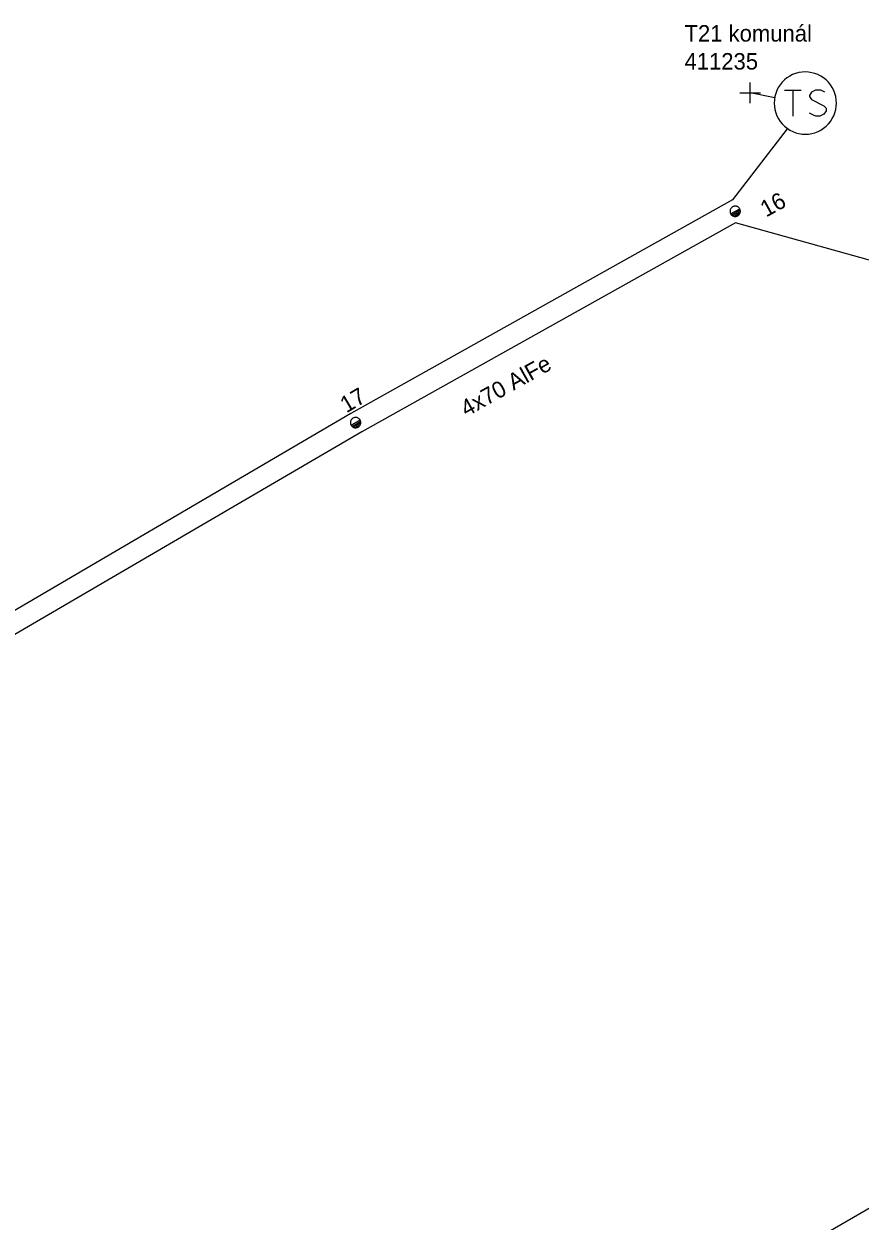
# Model space of a CAD drawing. Extents: x -540466 to -537383, y -1184038 to -1179972.
# Drawn here: x -537804.1 to -537753.3, y -1180377.4 to -1180304.7 of the extents above; entities that cross this region are included whole.
import ezdxf

# ---------------------------------------------------------------- set-up
doc = ezdxf.new("R2010")
doc.units = 0
for name, color, linetype in [('Vrstva 1', 7, 'Continuous'), ('Vrstva 13', 7, 'Continuous'), ('Vrstva 14', 7, 'Continuous'), ('Vrstva 2', 7, 'Continuous'), ('Vrstva 25', 7, 'Continuous'), ('Vrstva 26', 7, 'Continuous'), ('Vrstva 27', 7, 'Continuous'), ('Vrstva 34', 7, 'Continuous'), ('Vrstva 50', 7, 'Continuous'), ('Vrstva 59', 7, 'Continuous'), ('Vrstva 6', 7, 'Continuous'), ('Vrstva 8', 7, 'Continuous')]:
    doc.layers.add(name, color=color, linetype=linetype)

# ---------------------------------------------------------------- blocks, each defined once
blk = doc.blocks.new('NN440')
at = {"layer": 'Vrstva 2'}
for points in [[(0.63, 0), (0.63, 0.06), (0.62, 0.13), (0.6, 0.19), (0.58, 0.25), (0.55, 0.31), (0.51, 0.37), (0.47, 0.42), (0.42, 0.46), (0.37, 0.51), (0.32, 0.54), (0.26, 0.57), (0.2, 0.59), (0.13, 0.61), (0.07, 0.62), (0, 0.63), (-0.06, 0.62), (-0.13, 0.61), (-0.19, 0.59), (-0.26, 0.57), (-0.31, 0.54), (-0.37, 0.51), (-0.42, 0.46), (-0.47, 0.42), (-0.51, 0.37), (-0.54, 0.31), (-0.57, 0.25), (-0.6, 0.19), (-0.62, 0.13), (-0.63, 0.06), (-0.63, 0), (-0.63, -0.07), (-0.62, -0.14), (-0.6, -0.2), (-0.57, -0.26), (-0.54, -0.32), (-0.51, -0.37), (-0.47, -0.43), (-0.42, -0.47), (-0.37, -0.51), (-0.31, -0.55), (-0.26, -0.58), (-0.19, -0.6), (-0.13, -0.62), (-0.06, -0.63), (0, -0.63), (0.07, -0.63), (0.13, -0.62), (0.2, -0.6), (0.26, -0.58), (0.32, -0.55), (0.37, -0.51), (0.42, -0.47), (0.47, -0.43), (0.51, -0.37), (0.55, -0.32), (0.58, -0.26), (0.6, -0.2), (0.62, -0.14), (0.63, -0.07), (0.63, 0)], [(-0.63, 0), (0.63, 0)], [(-0.6, -0.18), (0.57, -0.18)], [(-0.51, -0.32), (0.5, -0.32)], [(-0.37, -0.47), (0.35, -0.47)]]:
    blk.add_lwpolyline(points, dxfattribs=at)
blk = doc.blocks.new('NN800')
at = {"layer": 'Vrstva 1'}
for points in [[(-0.442, 0.442), (0.442, -0.442)], [(-0.442, -0.442), (0.442, 0.442)]]:
    blk.add_lwpolyline(points, dxfattribs=at)
blk = doc.blocks.new('NN610')
at = {"layer": 'Vrstva 6'}
for points in [[(1.883, -0.001), (1.872, 0.196), (1.841, 0.392), (1.79, 0.583), (1.718, 0.768), (1.629, 0.943), (1.521, 1.109), (1.397, 1.263), (1.257, 1.403), (1.103, 1.527), (0.937, 1.635), (0.761, 1.725), (0.577, 1.796), (0.19, 1.878), (0.19, 1.878), (-0.007, 1.889), (-0.205, 1.878), (-0.401, 1.847), (-0.591, 1.796), (-0.777, 1.725), (-0.952, 1.635), (-1.118, 1.527), (-1.272, 1.403), (-1.412, 1.263), (-1.536, 1.109), (-1.644, 0.943), (-1.734, 0.768), (-1.805, 0.583), (-1.856, 0.392), (-1.887, 0.196), (-1.898, -0.001), (-1.887, -0.199), (-1.856, -0.395), (-1.805, -0.585), (-1.734, -0.77), (-1.644, -0.946), (-1.536, -1.112), (-1.411, -1.266), (-1.272, -1.405), (-1.118, -1.53), (-0.952, -1.638), (-0.776, -1.728), (-0.591, -1.799), (-0.401, -1.85), (-0.205, -1.881), (-0.007, -1.892), (0.19, -1.881), (0.385, -1.85), (0.577, -1.799), (0.761, -1.728), (0.937, -1.638), (1.103, -1.53), (1.257, -1.405), (1.397, -1.266), (1.521, -1.112), (1.629, -0.946), (1.718, -0.77), (1.79, -0.585), (1.841, -0.395), (1.872, -0.199), (1.883, -0.001)], [(-1.269, 0.782), (-0.261, 0.782)], [(-0.765, 0.782), (-0.765, -0.792)], [(1.188, 0.656), (0.936, 0.782), (0.621, 0.782), (0.369, 0.656), (0.243, 0.468), (0.243, 0.404), (0.369, 0.216), (1.125, -0.162), (1.251, -0.32), (1.251, -0.478), (1.125, -0.666), (0.873, -0.792), (0.621, -0.792), (0.495, -0.73), (0.243, -0.604)]]:
    blk.add_lwpolyline(points, dxfattribs=at)

msp = doc.modelspace()

# ---------------------------------------------------------------- linework, layer by layer
at = {"layer": 'Vrstva 1'}
msp.add_lwpolyline([(-537718.591, -1180328.331), (-537733.903, -1180324.349), (-537760.902, -1180316.828), (-537783.57, -1180329.507), (-537807.649, -1180343.561)], dxfattribs=at)
at = {"layer": 'Vrstva 50'}
msp.add_lwpolyline([(-537749.755, -1180374.876), (-537764.526, -1180383.433), (-537774.672, -1180385.885), (-537782.62, -1180390.235)], dxfattribs=at)
at = {"layer": 'Vrstva 59'}
msp.add_lwpolyline([(-537758.502, -1180309.229), (-537760.009, -1180308.927)], dxfattribs=at)
at = {"layer": 'Vrstva 8'}
msp.add_lwpolyline([(-537757.756, -1180311.117), (-537761.074, -1180315.423), (-537784.235, -1180328.381), (-537808.551, -1180342.632), (-537835.51, -1180366.15)], dxfattribs=at)

# ---------------------------------------------------------------- block references
at = {"layer": 'Vrstva 13'}
for p, xscale, yscale, rotation in [((-537760.914, -1180316.117), 0.5, 0.5, 28.875086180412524), ((-537783.949, -1180328.94), 0.49999999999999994, 0.5000000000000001, 30.633877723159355)]:
    msp.add_blockref('NN440', p, dxfattribs=dict(at, xscale=xscale, yscale=yscale, rotation=rotation))
at = {"layer": 'Vrstva 25', "rotation": 0.0699445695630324}
msp.add_blockref('NN610', (-537756.65, -1180309.55), dxfattribs=at)
at = {"layer": 'Vrstva 34', "rotation": 44.99999995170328}
msp.add_blockref('NN800', (-537760.009, -1180308.927), dxfattribs=at)

# ---------------------------------------------------------------- texts
at = {"layer": 'Vrstva 14'}
for s, rotation, p in [('16', 28.875, (-537759.033, -1180316.499)), ('17', 30.634, (-537784.503, -1180328.384))]:
    msp.add_text(s, height=1, rotation=rotation, dxfattribs=at).set_placement(p)
at = {"layer": 'Vrstva 2'}
msp.add_text('4x70 AlFe', height=1, rotation=29.22, dxfattribs=at).set_placement((-537777.219, -1180328.608))
at = {"layer": 'Vrstva 26'}
msp.add_text('411235', height=1, dxfattribs=at).set_placement((-537763.987, -1180307.516))
at = {"layer": 'Vrstva 27'}
msp.add_text('T21 komunál', height=1, dxfattribs=at).set_placement((-537763.987, -1180305.819))

doc.saveas('drawing.dxf')
